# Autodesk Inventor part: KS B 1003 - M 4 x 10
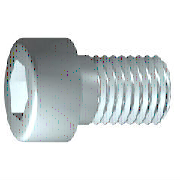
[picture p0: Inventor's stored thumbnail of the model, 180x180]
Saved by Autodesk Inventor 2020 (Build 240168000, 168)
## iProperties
Created: 2019-01
Part Number: KS B 1003 - M 4 x 10
Material: Acier, doux
Description: Vis à tôle à tête hexagonale
Document SubType Name: Modeling
Standard: KS B 1003
Designer: bruno
Standards Organization: KS
Language: fr-FR
Size Designation: M 4 x 10
Categories: <MemberInstance><Categories><Category DisplayName="Visserie" InternalName="e4da775c-781d-43d5-af7c-5136215cf5a6" Mnemonic="FSTN"><Category DisplayName="Vis" Int
Density: 7.85 g/cm^3
Appearance: Semi-poli
IsCustomPart: 0
Author: bruno
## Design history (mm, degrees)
sketch "Esquisse1"
  geometry: L1 (-1, 0)-(10, 0); L2 (10, 0)-(10, 2); L3 (10, 2)-(1.75, 2); L4 (1.75, 2)-(1.32, 2); L5 (1.32, 2)-(0, 2); L6 (0, 2)-(0, 3.5); L7 (0, 3.5)-(-4, 3.5); L8 (-4, 3.5)-(-4, 1.732); L9 (-4, 1.732)-(-2, 1.732); L10 (-2, 1.732)-(-1, 0); L11 (-6.8, 0)-(12.8, 0) reference; L12 (0, -0.7)-(0, 4.2) reference; L13 (1.75, 2)-(0, 2)
  constraints: 22 end point, 6 parallel, 2 collinear, 2 perpendicular, 1 horizontal, 1 point on line
  dimensions: "d1" = 8.25 distance from line of L3.end L2 (= GEL); "d2" = 0.42952 distance of L4.end L3.end (computed from GAL); "d3" = 4 distance between parallel lines of L8 L6 (= KOH); "d4" = 2 distance of L8.end L9.end (= INTI); "d5" = 60 deg angle of L10 L1; "d6" = 4 diameter of L3 L1 (= GD); "d7" = 4 diameter of L5 L1 (= BDM); "d8" = 3.4641 diameter of L9 L1 (= 1.1547 x SW); "d9" = 7 diameter of L7 L1 (= KOD); "d26" = 10 distance between parallel lines of L12 L2 (= NLG)
revolve "Corps" sketch "Esquisse1" stored, may be unused: angle "d10" = 90 deg
sketch "Esquisse2"
  geometry: L1 (0, -4.9)-(0, 4.9) reference; L2 (-4.9, 0)-(4.9, 0) reference; L3 (1.732, 0)-(0.866, -1.5); L4 (0.866, -1.5)-(-0.866, -1.5); L5 (-0.866, -1.5)-(-1.732, 0); L6 (-1.732, 0)-(-0.866, 1.5); L7 (-0.866, 1.5)-(0.866, 1.5); L8 (0.866, 1.5)-(1.732, 0); 2 further points
  constraints: 12 end point, 1 coincident, 1 horizontal alignment, 1 point on line, 12 other
extrude "Rainure" join sketch "Esquisse2" stored distance "d11" = 10; taper "d12" = 0 deg
workplane "Work Plane1"
fillet "Fillet2" dims "d30" = 0.1 (= R)
body "Solid1"
fillet "Congé1" dims "d17" = 0.4 (= RR)
feature "Filetage" dims "d13" = 8.25 (= GEL), "d14" = 0
chamfer "Chanfrein1" distance "d15" = 0.42941 (= -0.5 x SPD + 0.5 x GD); stored, may be unused: second distance "d16" = 0.42941 (= GUL), angle "d27" = 45 deg
other parameters: "GD" = 4 (= NND) [user parameter; used in 2 equation terms], "NLG" = 10 [user parameter; used in 1 equation term], "GEL" = 8.25 [user parameter; used in 2 equation terms], "KOD" = 7 [user parameter; used in 1 equation term], "KOH" = 4 [user parameter; used in 1 equation term], "INTI" = 2 [user parameter; used in 1 equation term], "GAL" = 0.42941 (= 0.61345 x PTC) [user parameter; used in 1 equation term], "GUL" = 0.42941 (= 0.61345 x PTC) [user parameter; used in 1 equation term], "BDM" = 4 (= NND) [user parameter; used in 1 equation term], "SW" = 3 [user parameter; used in 2 equation terms], "RR" = 0.4 [user parameter; used in 1 equation term], "SPD" = 3.14117 (= NND - 1.2269 x PTC) [user parameter; used in 1 equation term], "d19" = 0, "d28" = 0, "d29" = 0, "R" = 0.1 [user parameter; used in 1 equation term], "PHH" = 0.2 [user parameter], "GD1" = 3.14117 (= THREADDIA - 1.2269 x PTC) [user parameter], "THREADDIA" = 4 [user parameter; used in 1 equation term], "FAWI" = 45 deg [user parameter], "TPU" = 14.28571 (computed from PTC) [user parameter], "PTC" = 0.7 [user parameter; used in 5 equation terms], "NND" = 4 [user parameter; used in 3 equation terms], "TOA" = 30 deg [user parameter], "E0" = 3.465 (= 1.155 x SW) [user parameter]
